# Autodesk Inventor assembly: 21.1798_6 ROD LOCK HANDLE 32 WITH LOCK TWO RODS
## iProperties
Created: 2007-03
Part Number: 21.1798_6 ROD LOCK HANDLE 32 WITH LOCK TWO RODS
Document SubType Name: Assembly
Designer: Andy Moles
Author: Andy Moles
